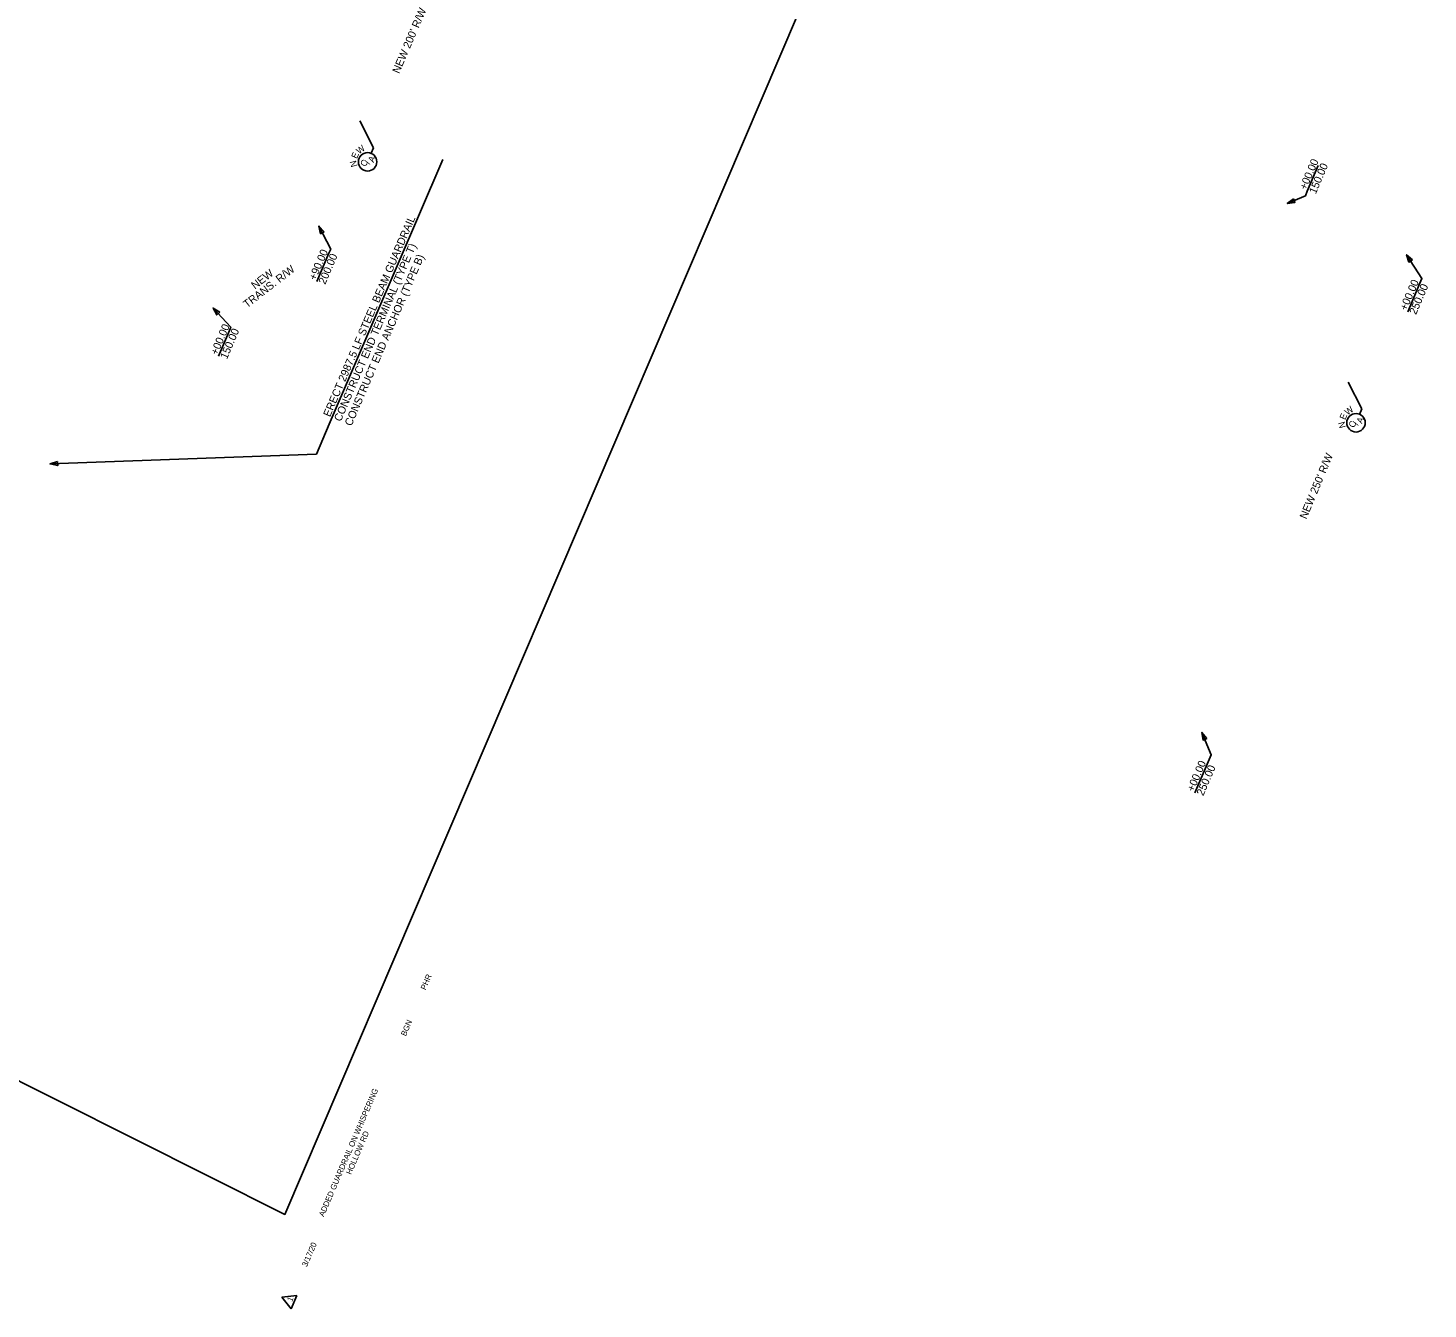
# Model space of a CAD drawing. Extents: x 1615013 to 1616950, y 1098171 to 1100198.
# Drawn here: x 1615872 to 1616950, y 1098171 to 1099157 of the extents above; entities that cross this region are included whole.
import ezdxf

# ---------------------------------------------------------------- set-up
doc = ezdxf.new("R2010")
doc.units = 0
for name, color, linetype in [('RD_EX_BldgChurch', 7, 'Continuous'), ('RD_EX_Driveway', 7, 'Continuous'), ('RD_EX_Fence_ChLk', 7, 'Continuous'), ('RD_EX_H2O_WetLd', 7, 'Continuous'), ('RD_EX_Misc_Golf_Teebox', 7, 'Continuous'), ('RD_EX_UT', 7, 'Continuous')]:
    doc.layers.add(name, color=color, linetype=linetype)

msp = doc.modelspace()

# ---------------------------------------------------------------- linework, layer by layer
at = {"layer": 'RD_EX_Driveway'}
msp.add_line((1616191.7, 1099055.7), (1616104.2, 1098851.8), dxfattribs=at)
msp.add_lwpolyline([(1616104.2, 1098851.8), (1616094.3, 1098828.8), (1615889.2, 1098821.3)], dxfattribs=at)
msp.add_lwpolyline([(1615895, 1098823.1), (1615889.2, 1098821.3), (1615895.1, 1098820)], close=True, dxfattribs=at)
at = {"layer": 'RD_EX_Fence_ChLk'}
for p, q in [((1616865.8, 1099051), (1616857.4, 1099031.3)), ((1616104, 1098983.5), (1616094.6, 1098961.6)), ((1616944.1, 1098960.4), (1616934.7, 1098938.4)), ((1616027.4, 1098923.9), (1616018.9, 1098904.1)), ((1616780.3, 1098590), (1616770.8, 1098568))]:
    msp.add_line(p, q, dxfattribs=at)
for points in [[(1616857.4, 1099031.3), (1616855.9, 1099027.7), (1616842, 1099021.7)], [(1616104, 1098983.5), (1616105.3, 1098986.5), (1616096.2, 1099004.3)], [(1616944.1, 1098960.4), (1616945.6, 1098964), (1616933.9, 1098982.3)], [(1616027.4, 1098923.9), (1616028.4, 1098926.4), (1616014.8, 1098941.2)], [(1616780.3, 1098590), (1616783.4, 1098597.4), (1616776.3, 1098614.6)]]:
    msp.add_lwpolyline(points, dxfattribs=at)
for points in [[(1616846.7, 1099025.4), (1616842, 1099021.7), (1616847.9, 1099022.6)], [(1616100.3, 1098999.8), (1616096.2, 1099004.3), (1616097.5, 1098998.4)], [(1616938.3, 1098978.3), (1616933.9, 1098982.3), (1616935.7, 1098976.6)], [(1616019.9, 1098938), (1616014.8, 1098941.2), (1616017.6, 1098935.9)], [(1616779.9, 1098609.9), (1616776.3, 1098614.6), (1616777.1, 1098608.7)]]:
    msp.add_lwpolyline(points, close=True, dxfattribs=at)
at = {"layer": 'RD_EX_H2O_WetLd'}
for p, q in [((1616138.3, 1099064.6), (1616127.8, 1099085.3)), ((1616136.5, 1099060.4), (1616138.3, 1099064.6)), ((1616899.5, 1098863.6), (1616888.9, 1098884.3)), ((1616897.7, 1098859.4), (1616899.5, 1098863.6))]:
    msp.add_line(p, q, dxfattribs=at)
for centre in [(1616133.7, 1099053.8), (1616894.9, 1098852.9)]:
    msp.add_circle(centre, 7.08, dxfattribs=at)
at = {"layer": 'RD_EX_Misc_Golf_Teebox'}
for p, q in [((1616067.7, 1098179.9), (1616079.3, 1098181.2)), ((1616067.7, 1098179.9), (1616074.8, 1098170.7)), ((1616074.8, 1098170.7), (1616079.3, 1098181.2))]:
    msp.add_line(p, q, dxfattribs=at)
at = {"layer": 'RD_EX_UT'}
msp.add_lwpolyline([(1615502.7, 1098507.9), (1615778.5, 1098389.7), (1616070.1, 1098243.5), (1616662.9, 1099630.3), (1616368.7, 1099765.8), (1616095.1, 1099888.9), (1615859, 1099986), (1615829.5, 1100008.4), (1615766.4, 1099858.4), (1615733.7, 1099872.1), (1615213.1, 1098634.6)], close=True, dxfattribs=at)
msp.add_lwpolyline([(1615502.7, 1098507.9), (1615778.5, 1098389.7), (1616070.1, 1098243.5), (1616662.9, 1099630.3), (1616368.7, 1099765.8), (1616095.1, 1099888.9), (1615859, 1099986), (1615829.5, 1100008.4), (1615766.4, 1099858.4), (1615733.7, 1099872.1), (1615213.1, 1098634.6)], close=True, dxfattribs=at)

# ---------------------------------------------------------------- texts
at = {"layer": 'RD_EX_BldgChurch'}
for s, rotation, p in [("NEW 200' R/W", 66.8024, (1616158, 1099121.3)), ('TRANS. R/W', 37.7478, (1616040.9, 1098941)), ('NEW', 37.7478, (1616047, 1098955.4)), ("NEW 250' R/W", 67.3945, (1616856.7, 1098778.3))]:
    msp.add_text(s, height=6, rotation=rotation, dxfattribs=at).set_placement(p)
at = {"layer": 'RD_EX_Driveway'}
for s, p in [('ERECT 2987.5 LF STEEL BEAM GUARDRAIL', (1616104.8, 1098857)), ('CONSTRUCT END TERMINAL (TYPE T)', (1616113.1, 1098853.4)), ('CONSTRUCT END ANCHOR (TYPE B)', (1616121.3, 1098849.9))]:
    msp.add_text(s, height=6, rotation=66.783, dxfattribs=at).set_placement(p)
at = {"layer": 'RD_EX_Fence_ChLk'}
for s, p in [('+00.00', (1616856.5, 1099031.7)), ('150.00', (1616863.9, 1099028.6)), ('+90.00', (1616093.7, 1098962.1)), ('200.00', (1616101.1, 1098959)), ('+00.00', (1616933.8, 1098938.8)), ('250.00', (1616941.1, 1098935.7)), ('+00.00', (1616018, 1098904.6)), ('150.00', (1616025.4, 1098901.4)), ('+00.00', (1616769.9, 1098568.5)), ('250.00', (1616777.3, 1098565.3))]:
    msp.add_text(s, height=6, rotation=66.8024, dxfattribs=at).set_placement(p)
at = {"layer": 'RD_EX_H2O_WetLd'}
for s, rotation, p in [('E', 66.7829, (1616125.5, 1099055.8)), ('W', 37.584, (1616127.3, 1099059.4)), ('N', 105.6962, (1616126, 1099050.6)), ('C', 66.783, (1616132.4, 1099049.7)), ('/', 66.783, (1616135.5, 1099051.6)), ('A', 66.783, (1616138.4, 1099052.9)), ('E', 66.7829, (1616886.6, 1098854.8)), ('W', 37.584, (1616888.5, 1098858.4)), ('A', 66.783, (1616899.5, 1098851.9)), ('N', 105.6962, (1616887.2, 1098849.6)), ('C', 66.783, (1616893.5, 1098848.7)), ('/', 66.783, (1616896.6, 1098850.6))]:
    msp.add_text(s, height=5, rotation=rotation, dxfattribs=at).set_placement(p)
at = {"layer": 'RD_EX_Misc_Golf_Teebox'}
for s, p in [('PHR', (1616178.4, 1098415.9)), ('BGN', (1616163.2, 1098380.4)), ('ADDED GUARDRAIL ON WHISPERING ', (1616100, 1098241.4)), ('HOLLOW RD', (1616121, 1098273.8)), ('3/17/20', (1616087, 1098202.8)), ('1', (1616075.5, 1098176))]:
    msp.add_text(s, height=4.4, rotation=66.7846, dxfattribs=at).set_placement(p)

doc.saveas('drawing.dxf')
